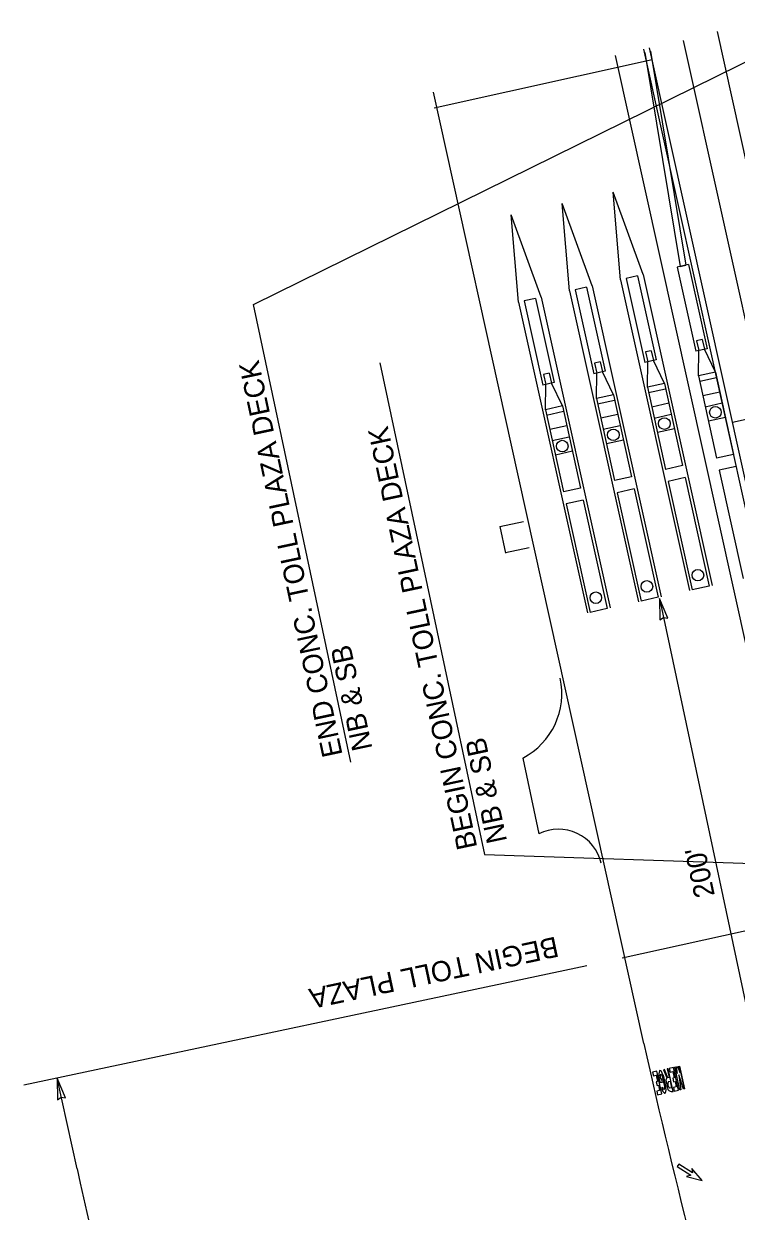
# Model space of a CAD drawing. Extents: x 578088 to 579220, y 1508751 to 1510400.
# Drawn here: x 578088 to 578333.4, y 1509907.9 to 1510317.1 of the extents above; entities that cross this region are included whole.
import ezdxf

# ---------------------------------------------------------------- set-up
doc = ezdxf.new("R2010")
doc.units = 0
for name, color, linetype in [('1', 7, 'Continuous'), ('18', 7, 'Continuous'), ('2', 7, 'Continuous'), ('20', 7, 'Continuous'), ('41', 7, 'Continuous'), ('52', 7, 'Continuous')]:
    doc.layers.add(name, color=color, linetype=linetype)

msp = doc.modelspace()

# ---------------------------------------------------------------- linework, layer by layer
at = {"layer": '1'}
msp.add_line((578559.88, 1509205.29), (578315.3, 1510311.37), dxfattribs=at)
at = {"layer": '18'}
for p, q in [((578471.12, 1509495.56), (578291.87, 1510306.19)), ((578301.41, 1510230.63), (578291.03, 1510259.06)), ((578293.6, 1510228.9), (578291.03, 1510259.06)), ((578283.84, 1510226.74), (578273.45, 1510255.17)), ((578276.03, 1510225.01), (578273.45, 1510255.17)), ((578266.26, 1510222.85), (578255.88, 1510251.28)), ((578258.45, 1510221.13), (578255.88, 1510251.28)), ((578317.03, 1510234.08), (578313.13, 1510233.22)), ((578313.13, 1510233.22), (578319.53, 1510204.25)), ((578317.03, 1510234.08), (578323.44, 1510205.11)), ((578293.6, 1510228.9), (578317.28, 1510121.82)), ((578299.46, 1510230.19), (578295.55, 1510229.33)), ((578295.55, 1510229.33), (578301.96, 1510200.36)), ((578299.46, 1510230.19), (578305.87, 1510201.22)), ((578301.41, 1510230.63), (578325.09, 1510123.54)), ((578276.03, 1510225.01), (578299.7, 1510117.93)), ((578281.88, 1510226.31), (578277.98, 1510225.45)), ((578277.98, 1510225.45), (578284.38, 1510196.47)), ((578281.88, 1510226.31), (578288.29, 1510197.34)), ((578283.84, 1510226.74), (578307.51, 1510119.66)), ((578258.45, 1510221.13), (578282.13, 1510114.04)), ((578264.31, 1510222.42), (578260.4, 1510221.56)), ((578260.4, 1510221.56), (578266.81, 1510192.59)), ((578264.31, 1510222.42), (578270.71, 1510193.45)), ((578266.26, 1510222.85), (578289.94, 1510115.77)), ((578321.71, 1510208.31), (578319.76, 1510207.88)), ((578319.76, 1510207.88), (578320.51, 1510204.46)), ((578321.71, 1510208.31), (578322.46, 1510204.9)), ((578304.13, 1510204.43), (578302.18, 1510203.99)), ((578302.18, 1510203.99), (578302.94, 1510200.58)), ((578304.13, 1510204.43), (578304.89, 1510201.01)), ((578323.44, 1510205.11), (578319.53, 1510204.25)), ((578320.39, 1510195.73), (578320.51, 1510204.46)), ((578326.25, 1510197.03), (578322.46, 1510204.9)), ((578286.56, 1510200.54), (578284.6, 1510200.11)), ((578284.6, 1510200.11), (578285.36, 1510196.69)), ((578286.56, 1510200.54), (578287.31, 1510197.12)), ((578305.87, 1510201.22), (578301.96, 1510200.36)), ((578302.82, 1510191.85), (578302.94, 1510200.58)), ((578308.68, 1510193.14), (578304.89, 1510201.01)), ((578268.98, 1510196.65), (578267.03, 1510196.22)), ((578267.03, 1510196.22), (578267.78, 1510192.8)), ((578268.98, 1510196.65), (578269.74, 1510193.24)), ((578288.29, 1510197.34), (578284.38, 1510196.47)), ((578285.24, 1510187.96), (578285.36, 1510196.69)), ((578291.1, 1510189.25), (578287.31, 1510197.12)), ((578326.25, 1510197.03), (578320.39, 1510195.73)), ((578320.39, 1510195.73), (578326.65, 1510167.42)), ((578326.25, 1510197.03), (578332.51, 1510168.71)), ((578270.71, 1510193.45), (578266.81, 1510192.59)), ((578267.67, 1510184.07), (578267.78, 1510192.8)), ((578273.53, 1510185.37), (578269.74, 1510193.24)), ((578308.68, 1510193.14), (578302.82, 1510191.85)), ((578302.82, 1510191.85), (578309.08, 1510163.53)), ((578309.11, 1510191.19), (578303.25, 1510189.89)), ((578308.68, 1510193.14), (578314.94, 1510164.83)), ((578326.68, 1510195.07), (578320.83, 1510193.78)), ((578291.1, 1510189.25), (578285.24, 1510187.96)), ((578285.24, 1510187.96), (578291.5, 1510159.64)), ((578291.53, 1510187.3), (578285.67, 1510186.01)), ((578291.1, 1510189.25), (578297.36, 1510160.94)), ((578327.76, 1510190.19), (578321.91, 1510188.9)), ((578273.53, 1510185.37), (578267.67, 1510184.07)), ((578267.67, 1510184.07), (578273.93, 1510155.76)), ((578273.96, 1510183.42), (578268.1, 1510182.12)), ((578273.53, 1510185.37), (578279.79, 1510157.05)), ((578310.19, 1510186.31), (578304.33, 1510185.01)), ((578328.63, 1510186.29), (578322.77, 1510184.99)), ((578292.61, 1510182.42), (578286.75, 1510181.12)), ((578311.05, 1510182.4), (578305.19, 1510181.11)), ((578329.71, 1510181.4), (578323.85, 1510180.11)), ((578275.04, 1510178.53), (578269.18, 1510177.24)), ((578293.48, 1510178.51), (578287.62, 1510177.22)), ((578312.13, 1510177.52), (578306.27, 1510176.22)), ((578275.9, 1510174.63), (578270.04, 1510173.33)), ((578294.56, 1510173.63), (578288.7, 1510172.34)), ((578276.98, 1510169.75), (578271.12, 1510168.45)), ((578332.51, 1510168.71), (578326.65, 1510167.42)), ((578314.94, 1510164.83), (578309.08, 1510163.53)), ((578333.43, 1510164.56), (578327.57, 1510163.27)), ((578327.57, 1510163.27), (578335.83, 1510125.92)), ((578297.36, 1510160.94), (578291.5, 1510159.64)), ((578315.86, 1510160.68), (578310, 1510159.38)), ((578310, 1510159.38), (578318.26, 1510122.03)), ((578315.86, 1510160.68), (578324.11, 1510123.33)), ((578279.79, 1510157.05), (578273.93, 1510155.76)), ((578298.28, 1510156.79), (578292.42, 1510155.49)), ((578292.42, 1510155.49), (578300.68, 1510118.15)), ((578298.28, 1510156.79), (578306.54, 1510119.44)), ((578280.7, 1510152.9), (578274.85, 1510151.61)), ((578274.85, 1510151.61), (578283.1, 1510114.26)), ((578280.7, 1510152.9), (578288.96, 1510115.55)), ((578324.11, 1510123.33), (578318.26, 1510122.03)), ((578306.54, 1510119.44), (578300.68, 1510118.15)), ((578288.96, 1510115.55), (578283.1, 1510114.26))]:
    msp.add_line(p, q, dxfattribs=at)
for centre in [(578326.24, 1510183.2), (578308.66, 1510179.31), (578291.09, 1510175.43), (578273.51, 1510171.54), (578320.21, 1510127.07), (578302.64, 1510123.19), (578285.06, 1510119.3)]:
    msp.add_circle(centre, 2, dxfattribs=at)
at = {"layer": '2'}
for p, q in [((578480.88, 1509497.72), (578301.64, 1510308.35)), ((578301.93, 1510307.24), (578314.1, 1510233.43)), ((578482.83, 1509498.15), (578303.59, 1510308.78)), ((578303.88, 1510307.67), (578316.06, 1510233.87)), ((578304.51, 1510304.62), (578229.33, 1510288)), ((578314.1, 1510233.43), (578316.06, 1510233.87)), ((578379.01, 1510190), (578332.14, 1510179.64)), ((578251.94, 1510143.85), (578253.95, 1510134.67)), ((578260.16, 1510145.47), (578251.97, 1510143.71)), ((578262.13, 1510136.54), (578253.93, 1510134.78)), ((578259.9, 1510064.06), (578265.45, 1510037.93)), ((578369.28, 1510011.7), (578294.1, 1509995.07))]:
    msp.add_line(p, q, dxfattribs=at)
for centre, radius, start, end in [((578248.34, 1510086.22), 25, 297.557, 12.4685), ((578272.22, 1510024.54), 15, 12.4685, 116.84)]:
    msp.add_arc(centre, radius, start, end, dxfattribs=at)
at = {"layer": '20'}
for p, q in [((578313.58, 1509957.79), (578313.9, 1509957.86)), ((578314.08, 1509955.51), (578313.58, 1509957.79)), ((578315.63, 1509950.05), (578313.9, 1509957.86)), ((578313.9, 1509957.86), (578315.63, 1509950.05)), ((578306.09, 1509956.13), (578304.63, 1509955.81)), ((578304.63, 1509955.81), (578304.91, 1509954.51)), ((578304.91, 1509954.51), (578305.89, 1509954.72)), ((578305.89, 1509954.72), (578306.36, 1509952.61)), ((578307.82, 1509948.32), (578306.09, 1509956.13)), ((578308.69, 1509956.71), (578308.37, 1509956.64)), ((578308.37, 1509956.64), (578309.51, 1509953.8)), ((578309.83, 1509953.89), (578308.69, 1509956.71)), ((578310, 1509957), (578309.67, 1509956.93)), ((578309.67, 1509956.93), (578310.32, 1509954)), ((578310.32, 1509954), (578309.83, 1509953.89)), ((578311.72, 1509949.19), (578310, 1509957)), ((578311.79, 1509957.39), (578310.32, 1509957.07)), ((578310.32, 1509957.07), (578310.61, 1509955.77)), ((578310.61, 1509955.77), (578311.59, 1509955.98)), ((578312.05, 1509953.87), (578311.57, 1509953.76)), ((578311.57, 1509953.76), (578311.85, 1509952.46)), ((578311.59, 1509955.98), (578312.05, 1509953.87)), ((578313.51, 1509949.58), (578311.79, 1509957.39)), ((578312.27, 1509957.52), (578312.59, 1509957.6)), ((578314, 1509949.69), (578312.27, 1509957.52)), ((578312.59, 1509957.6), (578313.1, 1509955.29)), ((578312.93, 1509957.64), (578313.25, 1509957.72)), ((578313.1, 1509955.29), (578312.93, 1509957.64)), ((578313.25, 1509957.72), (578314.08, 1509955.51)), ((578315.3, 1509949.98), (578313.7, 1509954.91)), ((578313.7, 1509954.91), (578314.33, 1509949.76)), ((578306.36, 1509952.61), (578305.87, 1509952.5)), ((578305.87, 1509952.5), (578306.16, 1509951.2)), ((578306.16, 1509951.2), (578306.65, 1509951.31)), ((578306.65, 1509951.31), (578307.04, 1509949.52)), ((578307.32, 1509953.5), (578307.61, 1509953.57)), ((578307.9, 1509952.27), (578307.32, 1509952.14)), ((578307.61, 1509953.57), (578307.9, 1509952.27)), ((578307.91, 1509949.77), (578307.94, 1509950.67)), ((578309.17, 1509952.99), (578309.87, 1509949.87)), ((578310.08, 1509952.58), (578310.61, 1509952.69)), ((578311.11, 1509950.42), (578310.56, 1509950.29)), ((578310.61, 1509952.69), (578311.11, 1509950.42)), ((578312.74, 1509950.78), (578311.76, 1509950.56)), ((578311.76, 1509950.56), (578312.05, 1509949.26)), ((578311.85, 1509952.46), (578312.34, 1509952.57)), ((578312.05, 1509949.26), (578313.51, 1509949.58)), ((578312.34, 1509952.57), (578312.74, 1509950.78)), ((578314.33, 1509949.76), (578314, 1509949.69)), ((578315.63, 1509950.05), (578315.3, 1509949.98)), ((578307.04, 1509949.52), (578306.06, 1509949.3)), ((578306.06, 1509949.3), (578306.35, 1509948)), ((578306.35, 1509948), (578307.82, 1509948.32)), ((578311.4, 1509949.11), (578311.72, 1509949.19)), ((578313.66, 1509924.13), (578313.12, 1509923.28)), ((578313.12, 1509923.28), (578317.82, 1509920.28)), ((578318.36, 1509921.12), (578313.66, 1509924.13)), ((578321.68, 1509918.42), (578318.15, 1509922.64)), ((578318.15, 1509922.64), (578318.36, 1509921.12)), ((578317.82, 1509920.28), (578316.35, 1509919.83)), ((578316.35, 1509919.83), (578321.68, 1509918.42))]:
    msp.add_line(p, q, dxfattribs=at)
for points in [[(578307.32, 1509952.14), (578306.8, 1509954.46)], [(578307.19, 1509954.09), (578307.32, 1509953.5)], [(578308.83, 1509950.84), (578308.07, 1509954.28)], [(578308.27, 1509954.78), (578309.22, 1509950.46)]]:
    msp.add_lwpolyline(points, dxfattribs=at)
for centre, major_axis, ratio, start_param, end_param in [((578308.01, 1509952.46), (0.86, -3.91), 0.225, 2.156482, 4.126703), ((578308.01, 1509952.46), (-0.58, 2.6), 0.225, 5.435123, 7.131247), ((578310.82, 1509951.72), (0.58, -2.6), 0.625, 3.662797, 4.068888), ((578308.01, 1509952.46), (0.86, -3.91), 0.225, 5.421015, 7.268296), ((578308.01, 1509952.46), (-0.58, 2.6), 0.225, 2.279423, 3.989655), ((578310.72, 1509951.52), (-0.27, 1.31), 0.625, 0.515234, 2.646405), ((578310.82, 1509951.72), (0.58, -2.6), 0.625, 5.35589, 6.283185)]:
    msp.add_ellipse(centre, major_axis=major_axis, ratio=ratio, start_param=start_param, end_param=end_param, dxfattribs=at)
at = {"layer": '41'}
for p, q in [((578374.47, 1510099.38), (578326.92, 1510314.41)), ((578258.43, 1510160.98), (578229.13, 1510293.53)), ((578301.62, 1509965.7), (578258.43, 1510160.98))]:
    msp.add_line(p, q, dxfattribs=at)
msp.add_arc((580335.96, 1510415.53), 2083.48, 192.46859, 200.71859, dxfattribs=at)
at = {"layer": '52'}
for p, q in [((578167.13, 1510220.3), (578363.2, 1510317.1)), ((578200.66, 1510062.58), (578167.13, 1510220.3)), ((578210.63, 1510200.27), (578246.65, 1510030.8)), ((578306.96, 1510119.01), (578349.08, 1509920.82)), ((578306.96, 1510119.01), (578307.15, 1510111.63)), ((578309.84, 1510112.22), (578306.96, 1510119.01)), ((578307.15, 1510111.63), (578308.4, 1510112.47)), ((578308.4, 1510112.47), (578309.84, 1510112.22)), ((578246.65, 1510030.8), (578427.87, 1510024.65)), ((578281.95, 1509992.49), (578087.97, 1509951.26)), ((578106.33, 1509922.52), (578099.44, 1509953.7)), ((578099.44, 1509953.7), (578099.64, 1509946.31)), ((578102.32, 1509946.91), (578099.44, 1509953.7)), ((578099.64, 1509946.31), (578100.89, 1509947.15)), ((578100.89, 1509947.15), (578102.32, 1509946.91))]:
    msp.add_line(p, q, dxfattribs=at)
msp.add_arc((580335.96, 1510415.53), 2283.48, 192.46859, 200.71859, dxfattribs=at)

# ---------------------------------------------------------------- texts
for s, rotation, p in [('END CONC. TOLL PLAZA DECK', 102, (578197.84, 1510065.17)), ('BEGIN CONC. TOLL PLAZA DECK', 102, (578244.24, 1510033.29)), ('NB & SB', 102, (578208.12, 1510067.36)), ('NB & SB', 102, (578254.51, 1510035.47)), ("200'", 102, (578326.08, 1510016.75)), ('BEGIN TOLL PLAZA', 192, (578271.29, 1510002.57))]:
    msp.add_text(s, height=7, rotation=rotation, dxfattribs=at).set_placement(p)

doc.saveas('drawing.dxf')
